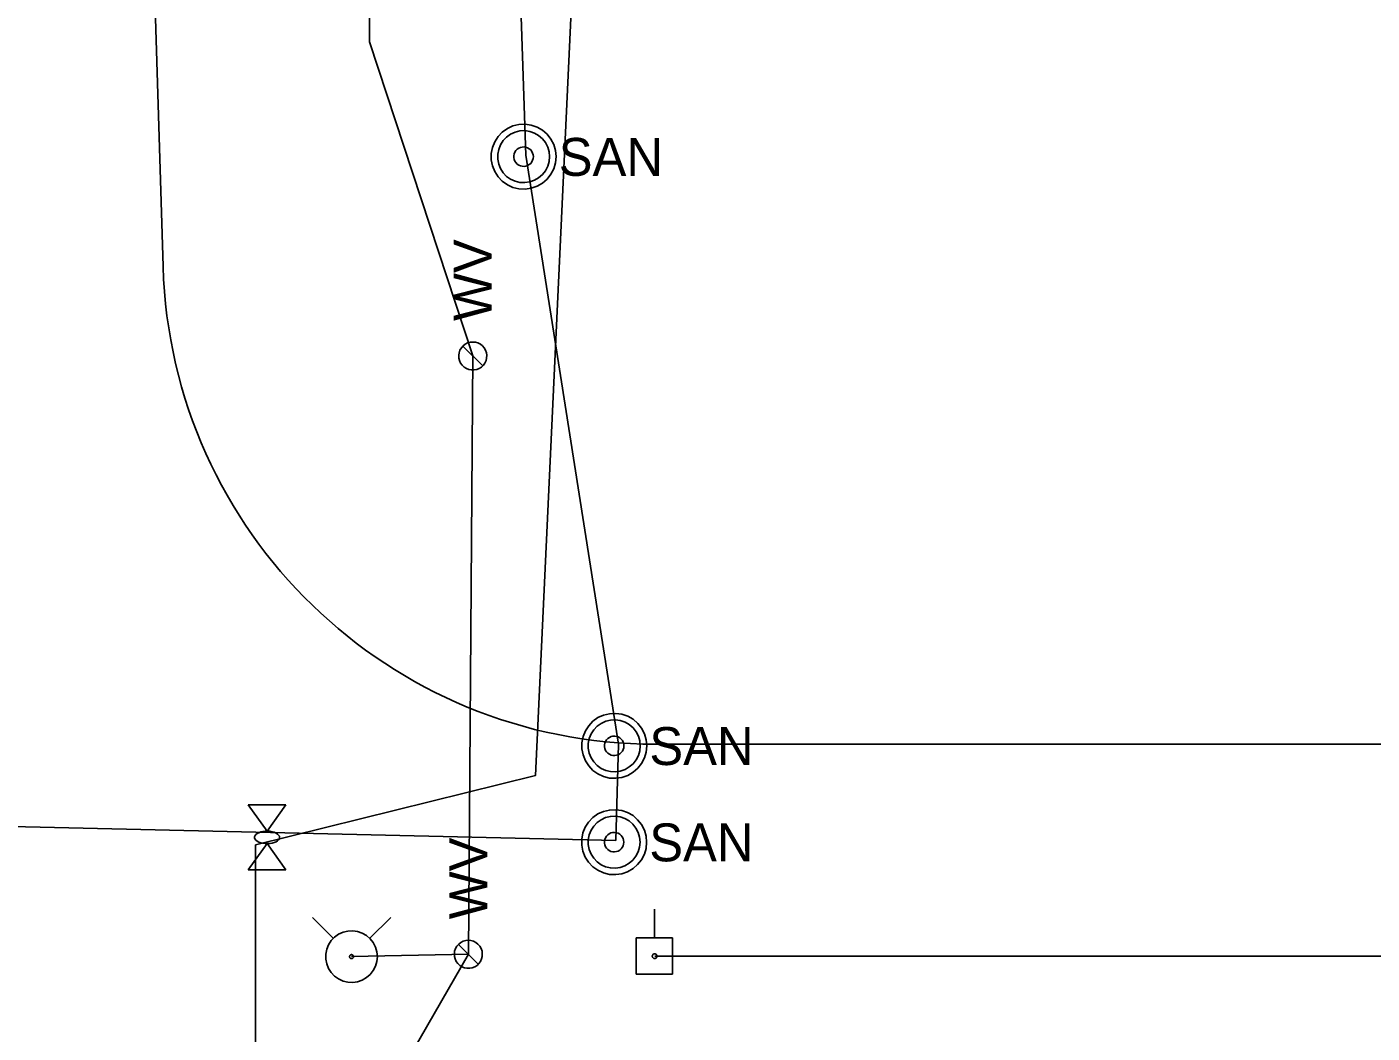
# Model space of a CAD drawing. Extents: x 596028 to 606371, y 330010 to 403088.
# Drawn here: x 605009.9 to 605146.4, y 331373.7 to 331475.9 of the extents above; entities that cross this region are included whole.
import ezdxf

# ---------------------------------------------------------------- set-up
doc = ezdxf.new("R2010")
doc.units = 0
for name, color, linetype in [('E_UTL_AG', 7, 'Continuous'), ('E_UTL_E_Bold', 7, 'Continuous'), ('E_UTL_E_UG', 7, 'Continuous'), ('E_UTL_EPowerPole', 7, 'Continuous'), ('E_UTL_Overhead', 7, 'Continuous'), ('E_UTL_SAN_MH', 7, 'Continuous'), ('E_UTL_SAN_UG', 7, 'Continuous'), ('E_UTL_SAN_UG_MMSD', 7, 'Continuous'), ('E_UTL_W', 7, 'Continuous'), ('E_UTL_W_UG', 7, 'Continuous'), ('E_UTL_WHydrant', 7, 'Continuous')]:
    doc.layers.add(name, color=color, linetype=linetype)

# ---------------------------------------------------------------- blocks, each defined once
blk = doc.blocks.new('MTR')
at = {"layer": 'E_UTL_AG'}
for points in [[(-11, 20), (11, 20), (0, 4)], [(-11, -20), (11, -20), (0, -4)]]:
    blk.add_lwpolyline(points, close=True, dxfattribs=at)
blk.add_ellipse((0, 0), major_axis=(7.62, 0), ratio=0.5, dxfattribs=at)

msp = doc.modelspace()

# ---------------------------------------------------------------- linework, layer by layer
at = {"layer": 'E_UTL_E_Bold'}
for points in [[(605032.33, 331396.87), (605036.14, 331396.87)], [(605034.24, 331394.21), (605032.33, 331396.87)], [(605036.14, 331396.87), (605034.24, 331394.21)], [(605035.51, 331393.57), (605035.49, 331393.69), (605035.42, 331393.81), (605035.31, 331393.91), (605035.16, 331394.01), (605034.97, 331394.09), (605034.77, 331394.15), (605034.54, 331394.19), (605034.3, 331394.21), (605034.06, 331394.2), (605033.82, 331394.17), (605033.6, 331394.12), (605033.41, 331394.05), (605033.24, 331393.96), (605033.11, 331393.86), (605033.02, 331393.75), (605032.97, 331393.63), (605032.97, 331393.51), (605033.02, 331393.39), (605033.11, 331393.28), (605033.24, 331393.18), (605033.41, 331393.09), (605033.6, 331393.02), (605033.82, 331392.97), (605034.06, 331392.94), (605034.3, 331392.94), (605034.54, 331392.95), (605034.77, 331392.99), (605034.97, 331393.05), (605035.16, 331393.13), (605035.31, 331393.23), (605035.42, 331393.33), (605035.49, 331393.45), (605035.51, 331393.57)], [(605034.24, 331392.94), (605032.33, 331390.27)], [(605036.14, 331390.27), (605034.24, 331392.94)], [(605032.33, 331390.27), (605036.14, 331390.27)]]:
    msp.add_lwpolyline(points, dxfattribs=at)
at = {"layer": 'E_UTL_E_UG'}
msp.add_lwpolyline([(604870.57, 331033.54), (605033.08, 331252.35), (605033.08, 331392.8), (605061.51, 331399.86), (605069.48, 331571.07), (605141.68, 331571.07)], dxfattribs=at)
at = {"layer": 'E_UTL_EPowerPole'}
for points in [[(605073.57, 331383.36), (605073.57, 331386.27)], [(605075.41, 331383.36), (605071.72, 331383.36)], [(605071.72, 331383.36), (605071.72, 331379.67)], [(605075.41, 331379.67), (605075.41, 331383.36)], [(605073.84, 331381.52), (605073.83, 331381.56), (605073.82, 331381.61), (605073.8, 331381.65), (605073.77, 331381.68), (605073.74, 331381.71), (605073.7, 331381.73), (605073.66, 331381.75), (605073.61, 331381.76), (605073.57, 331381.75), (605073.52, 331381.74), (605073.48, 331381.72), (605073.44, 331381.7), (605073.41, 331381.66), (605073.39, 331381.63), (605073.37, 331381.58), (605073.36, 331381.54), (605073.36, 331381.49), (605073.37, 331381.45), (605073.39, 331381.41), (605073.41, 331381.37), (605073.44, 331381.34), (605073.48, 331381.31), (605073.52, 331381.29), (605073.57, 331381.28), (605073.61, 331381.28), (605073.66, 331381.29), (605073.7, 331381.3), (605073.74, 331381.32), (605073.77, 331381.35), (605073.8, 331381.39), (605073.82, 331381.43), (605073.83, 331381.47), (605073.84, 331381.52)], [(605071.72, 331379.67), (605075.41, 331379.67)]]:
    msp.add_lwpolyline(points, dxfattribs=at)
at = {"layer": 'E_UTL_Overhead'}
msp.add_lwpolyline([(605073.6, 331381.52), (605283.74, 331381.52)], dxfattribs=at)
at = {"layer": 'E_UTL_SAN_MH'}
for points in [[(605063.59, 331462.69), (605063.53, 331463.31), (605063.36, 331463.91), (605063.07, 331464.47), (605062.68, 331464.97), (605062.21, 331465.38), (605061.66, 331465.69), (605061.07, 331465.9), (605060.45, 331465.98), (605059.82, 331465.95), (605059.21, 331465.81), (605058.64, 331465.55), (605058.13, 331465.18), (605057.7, 331464.73), (605057.36, 331464.2), (605057.13, 331463.62), (605057.01, 331463), (605057.01, 331462.37), (605057.13, 331461.76), (605057.36, 331461.18), (605057.7, 331460.65), (605058.13, 331460.19), (605058.64, 331459.83), (605059.21, 331459.57), (605059.82, 331459.42), (605060.45, 331459.39), (605061.07, 331459.48), (605061.66, 331459.69), (605062.21, 331460), (605062.68, 331460.41), (605063.07, 331460.9), (605063.36, 331461.46), (605063.53, 331462.06), (605063.59, 331462.69)], [(605062.93, 331462.69), (605062.88, 331463.19), (605062.74, 331463.67), (605062.51, 331464.12), (605062.2, 331464.51), (605061.82, 331464.84), (605061.39, 331465.09), (605060.91, 331465.25), (605060.42, 331465.33), (605059.92, 331465.3), (605059.43, 331465.18), (605058.97, 331464.97), (605058.56, 331464.68), (605058.22, 331464.32), (605057.95, 331463.9), (605057.76, 331463.43), (605057.66, 331462.94), (605057.66, 331462.44), (605057.76, 331461.94), (605057.95, 331461.48), (605058.22, 331461.06), (605058.56, 331460.69), (605058.97, 331460.4), (605059.43, 331460.19), (605059.92, 331460.08), (605060.42, 331460.05), (605060.91, 331460.12), (605061.39, 331460.29), (605061.82, 331460.54), (605062.2, 331460.87), (605062.51, 331461.26), (605062.74, 331461.71), (605062.88, 331462.19), (605062.93, 331462.69)], [(605061.28, 331462.69), (605061.26, 331462.88), (605061.21, 331463.06), (605061.12, 331463.22), (605061.01, 331463.37), (605060.87, 331463.49), (605060.7, 331463.59), (605060.52, 331463.65), (605060.34, 331463.68), (605060.15, 331463.67), (605059.97, 331463.62), (605059.8, 331463.55), (605059.64, 331463.44), (605059.51, 331463.3), (605059.41, 331463.14), (605059.34, 331462.97), (605059.31, 331462.78), (605059.31, 331462.59), (605059.34, 331462.41), (605059.41, 331462.23), (605059.51, 331462.08), (605059.64, 331461.94), (605059.8, 331461.83), (605059.97, 331461.75), (605060.15, 331461.71), (605060.34, 331461.7), (605060.52, 331461.73), (605060.7, 331461.79), (605060.87, 331461.88), (605061.01, 331462.01), (605061.12, 331462.15), (605061.21, 331462.32), (605061.26, 331462.5), (605061.28, 331462.69)], [(605072.79, 331402.87), (605072.73, 331403.49), (605072.56, 331404.09), (605072.27, 331404.65), (605071.88, 331405.15), (605071.41, 331405.56), (605070.86, 331405.87), (605070.27, 331406.08), (605069.65, 331406.16), (605069.02, 331406.13), (605068.41, 331405.99), (605067.84, 331405.73), (605067.33, 331405.36), (605066.9, 331404.91), (605066.56, 331404.38), (605066.33, 331403.8), (605066.21, 331403.18), (605066.21, 331402.55), (605066.33, 331401.94), (605066.56, 331401.36), (605066.9, 331400.83), (605067.33, 331400.37), (605067.84, 331400.01), (605068.41, 331399.75), (605069.02, 331399.6), (605069.65, 331399.57), (605070.27, 331399.66), (605070.86, 331399.87), (605071.41, 331400.18), (605071.88, 331400.59), (605072.27, 331401.08), (605072.56, 331401.64), (605072.73, 331402.24), (605072.79, 331402.87)], [(605072.13, 331402.87), (605072.08, 331403.37), (605071.94, 331403.85), (605071.71, 331404.3), (605071.4, 331404.69), (605071.02, 331405.02), (605070.59, 331405.27), (605070.11, 331405.43), (605069.62, 331405.51), (605069.12, 331405.48), (605068.63, 331405.36), (605068.17, 331405.15), (605067.76, 331404.86), (605067.42, 331404.5), (605067.15, 331404.08), (605066.96, 331403.61), (605066.86, 331403.12), (605066.86, 331402.62), (605066.96, 331402.12), (605067.15, 331401.66), (605067.42, 331401.24), (605067.76, 331400.87), (605068.17, 331400.58), (605068.63, 331400.37), (605069.12, 331400.26), (605069.62, 331400.23), (605070.11, 331400.3), (605070.59, 331400.47), (605071.02, 331400.72), (605071.4, 331401.05), (605071.71, 331401.44), (605071.94, 331401.89), (605072.08, 331402.37), (605072.13, 331402.87)], [(605070.48, 331402.87), (605070.46, 331403.06), (605070.41, 331403.24), (605070.32, 331403.4), (605070.21, 331403.55), (605070.07, 331403.67), (605069.9, 331403.77), (605069.72, 331403.83), (605069.54, 331403.86), (605069.35, 331403.85), (605069.17, 331403.8), (605069, 331403.73), (605068.84, 331403.62), (605068.71, 331403.48), (605068.61, 331403.32), (605068.54, 331403.15), (605068.51, 331402.96), (605068.51, 331402.77), (605068.54, 331402.59), (605068.61, 331402.41), (605068.71, 331402.26), (605068.84, 331402.12), (605069, 331402.01), (605069.17, 331401.93), (605069.35, 331401.89), (605069.54, 331401.88), (605069.72, 331401.91), (605069.9, 331401.97), (605070.07, 331402.06), (605070.21, 331402.19), (605070.32, 331402.33), (605070.41, 331402.5), (605070.46, 331402.68), (605070.48, 331402.87)], [(605072.78, 331393.09), (605072.72, 331393.71), (605072.55, 331394.31), (605072.26, 331394.87), (605071.87, 331395.37), (605071.4, 331395.78), (605070.85, 331396.09), (605070.26, 331396.3), (605069.64, 331396.38), (605069.01, 331396.35), (605068.4, 331396.21), (605067.83, 331395.95), (605067.32, 331395.58), (605066.89, 331395.13), (605066.55, 331394.6), (605066.32, 331394.02), (605066.2, 331393.4), (605066.2, 331392.77), (605066.32, 331392.16), (605066.55, 331391.58), (605066.89, 331391.05), (605067.32, 331390.59), (605067.83, 331390.23), (605068.4, 331389.97), (605069.01, 331389.82), (605069.64, 331389.79), (605070.26, 331389.88), (605070.85, 331390.09), (605071.4, 331390.4), (605071.87, 331390.81), (605072.26, 331391.3), (605072.55, 331391.86), (605072.72, 331392.46), (605072.78, 331393.09)], [(605072.12, 331393.09), (605072.07, 331393.59), (605071.93, 331394.07), (605071.7, 331394.52), (605071.39, 331394.91), (605071.01, 331395.24), (605070.58, 331395.49), (605070.1, 331395.65), (605069.61, 331395.73), (605069.11, 331395.7), (605068.62, 331395.58), (605068.16, 331395.37), (605067.75, 331395.08), (605067.41, 331394.72), (605067.14, 331394.3), (605066.95, 331393.83), (605066.85, 331393.34), (605066.85, 331392.84), (605066.95, 331392.34), (605067.14, 331391.88), (605067.41, 331391.46), (605067.75, 331391.09), (605068.16, 331390.8), (605068.62, 331390.59), (605069.11, 331390.48), (605069.61, 331390.45), (605070.1, 331390.52), (605070.58, 331390.69), (605071.01, 331390.94), (605071.39, 331391.27), (605071.7, 331391.66), (605071.93, 331392.11), (605072.07, 331392.59), (605072.12, 331393.09)], [(605070.47, 331393.09), (605070.45, 331393.28), (605070.4, 331393.46), (605070.31, 331393.62), (605070.2, 331393.77), (605070.06, 331393.89), (605069.89, 331393.99), (605069.71, 331394.05), (605069.53, 331394.08), (605069.34, 331394.07), (605069.16, 331394.02), (605068.99, 331393.95), (605068.83, 331393.84), (605068.7, 331393.7), (605068.6, 331393.54), (605068.53, 331393.37), (605068.5, 331393.18), (605068.5, 331392.99), (605068.53, 331392.81), (605068.6, 331392.63), (605068.7, 331392.48), (605068.83, 331392.34), (605068.99, 331392.23), (605069.16, 331392.15), (605069.34, 331392.11), (605069.53, 331392.1), (605069.71, 331392.13), (605069.89, 331392.19), (605070.06, 331392.28), (605070.2, 331392.41), (605070.31, 331392.55), (605070.4, 331392.72), (605070.45, 331392.9), (605070.47, 331393.09)]]:
    msp.add_lwpolyline(points, dxfattribs=at)
at = {"layer": 'E_UTL_SAN_UG'}
for p, q in [((605060.52, 331462.84), (605048.95, 331795.33)), ((605069.91, 331403.03), (605060.52, 331462.84)), ((605069.64, 331393.24), (605069.91, 331403.03)), ((604991.18, 331395.06), (605069.64, 331393.24))]:
    msp.add_line(p, q, dxfattribs=at)
at = {"layer": 'E_UTL_SAN_UG_MMSD'}
for p, q in [((605023.68, 331451.52), (605012.41, 331824.88)), ((605073.66, 331403.03), (605338.2, 331403.03))]:
    msp.add_line(p, q, dxfattribs=at)
msp.add_arc((605073.66, 331453.03), 50, 181.7295, 270, dxfattribs=at)
at = {"layer": 'E_UTL_W'}
for points in [[(605055.13, 331443.87), (605054.86, 331443.85), (605054.6, 331443.77), (605054.36, 331443.65), (605054.15, 331443.48), (605053.97, 331443.27), (605053.83, 331443.04), (605053.74, 331442.78), (605053.71, 331442.52), (605053.72, 331442.24), (605053.78, 331441.98), (605053.89, 331441.73), (605054.05, 331441.51), (605054.25, 331441.33), (605054.48, 331441.18), (605054.73, 331441.08), (605054.99, 331441.03), (605055.27, 331441.03), (605055.53, 331441.08), (605055.78, 331441.18), (605056.01, 331441.33), (605056.21, 331441.51), (605056.36, 331441.73), (605056.48, 331441.98), (605056.54, 331442.24), (605056.55, 331442.52), (605056.52, 331442.78), (605056.43, 331443.04), (605056.29, 331443.27), (605056.11, 331443.48), (605055.9, 331443.65), (605055.66, 331443.77), (605055.4, 331443.85), (605055.13, 331443.87)], [(605056.14, 331441.44), (605054.12, 331443.46)], [(605054.68, 331383.12), (605054.41, 331383.1), (605054.15, 331383.02), (605053.91, 331382.9), (605053.7, 331382.73), (605053.52, 331382.52), (605053.38, 331382.29), (605053.29, 331382.03), (605053.26, 331381.77), (605053.27, 331381.49), (605053.33, 331381.23), (605053.44, 331380.98), (605053.6, 331380.76), (605053.8, 331380.58), (605054.03, 331380.43), (605054.28, 331380.33), (605054.54, 331380.28), (605054.82, 331380.28), (605055.08, 331380.33), (605055.33, 331380.43), (605055.56, 331380.58), (605055.76, 331380.76), (605055.91, 331380.98), (605056.03, 331381.23), (605056.09, 331381.49), (605056.1, 331381.77), (605056.07, 331382.03), (605055.98, 331382.29), (605055.84, 331382.52), (605055.66, 331382.73), (605055.45, 331382.9), (605055.21, 331383.02), (605054.95, 331383.1), (605054.68, 331383.12)], [(605055.69, 331380.69), (605053.67, 331382.71)]]:
    msp.add_lwpolyline(points, dxfattribs=at)
at = {"layer": 'E_UTL_W_UG'}
for points in [[(604662.85, 330776.78), (604719.99, 330861.17), (604771.51, 330900.13), (604792.62, 330926.22), (604804.59, 330947.13), (605054.68, 331381.7), (605055.13, 331442.45), (605044.65, 331474.36), (605047.01, 331851.63), (605038.36, 332278.66), (605035.8, 332410.28), (605072.23, 332411.32), (605076.98, 332411.12), (605079.88, 332411.16)], [(605042.82, 331381.47), (605054.68, 331381.7)]]:
    msp.add_lwpolyline(points, dxfattribs=at)
at = {"layer": 'E_UTL_WHydrant'}
for points in [[(605040.99, 331383.3), (605038.84, 331385.44)], [(605044.66, 331383.3), (605046.8, 331385.44)], [(605045.44, 331381.47), (605045.4, 331381.96), (605045.25, 331382.44), (605045.03, 331382.89), (605044.72, 331383.28), (605044.34, 331383.6), (605043.91, 331383.85), (605043.44, 331384.02), (605042.94, 331384.09), (605042.45, 331384.06), (605041.96, 331383.95), (605041.51, 331383.74), (605041.1, 331383.45), (605040.76, 331383.09), (605040.49, 331382.67), (605040.3, 331382.21), (605040.21, 331381.72), (605040.21, 331381.22), (605040.3, 331380.73), (605040.49, 331380.27), (605040.76, 331379.85), (605041.1, 331379.49), (605041.51, 331379.2), (605041.96, 331378.99), (605042.45, 331378.87), (605042.94, 331378.85), (605043.44, 331378.92), (605043.91, 331379.08), (605044.34, 331379.33), (605044.72, 331379.66), (605045.03, 331380.05), (605045.25, 331380.49), (605045.4, 331380.97), (605045.44, 331381.47)], [(605043.02, 331381.47), (605043.02, 331381.51), (605043.01, 331381.54), (605042.99, 331381.58), (605042.96, 331381.61), (605042.94, 331381.63), (605042.9, 331381.65), (605042.87, 331381.66), (605042.83, 331381.67), (605042.79, 331381.67), (605042.75, 331381.66), (605042.72, 331381.64), (605042.69, 331381.62), (605042.66, 331381.59), (605042.64, 331381.56), (605042.63, 331381.52), (605042.62, 331381.49), (605042.62, 331381.45), (605042.63, 331381.41), (605042.64, 331381.38), (605042.66, 331381.34), (605042.69, 331381.32), (605042.72, 331381.29), (605042.75, 331381.28), (605042.79, 331381.27), (605042.83, 331381.27), (605042.87, 331381.27), (605042.9, 331381.28), (605042.94, 331381.3), (605042.96, 331381.33), (605042.99, 331381.36), (605043.01, 331381.39), (605043.02, 331381.43), (605043.02, 331381.47)]]:
    msp.add_lwpolyline(points, dxfattribs=at)

# ---------------------------------------------------------------- block references
at = {"layer": 'E_UTL_E_Bold', "xscale": 2.95275e-05, "yscale": 2.95275e-05}
msp.add_blockref('MTR', (605033.08, 331392.8), dxfattribs=at)

# ---------------------------------------------------------------- texts
at = {"layer": 'E_UTL_SAN_MH'}
for p in [(605063.86, 331460.74), (605073.06, 331400.92), (605073.05, 331391.14)]:
    msp.add_text('SAN', height=3.849, dxfattribs=at).set_placement(p)
at = {"layer": 'E_UTL_W'}
for p in [(605057.05, 331446.01), (605056.6, 331385.26)]:
    msp.add_text('WV', height=3.85, rotation=90, dxfattribs=at).set_placement(p)

doc.saveas('drawing.dxf')
